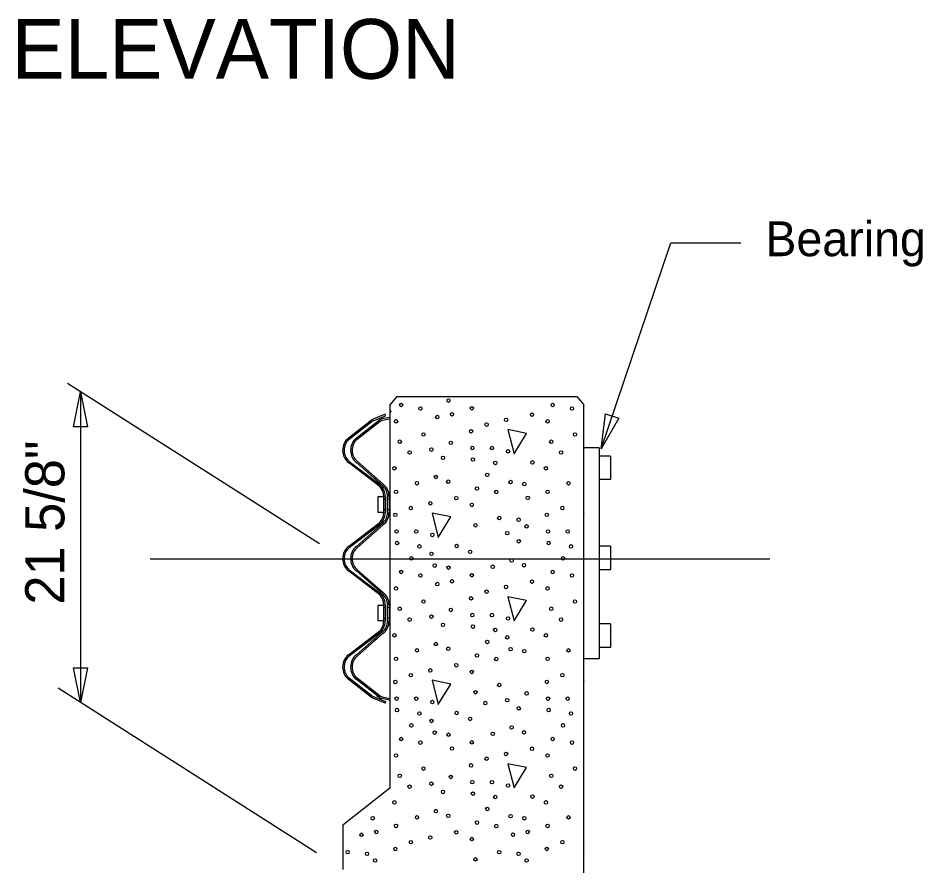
# Model space of a CAD drawing. Extents: x 0 to 34, y 0 to 22.
# Drawn here: x 10.612 to 14.256, y 4.131 to 7.539 of the extents above; entities that cross this region are included whole.
import ezdxf

# ---------------------------------------------------------------- set-up
doc = ezdxf.new("R2010")
doc.units = 0
doc.layers.add('ST_Details', color=7, linetype='Continuous')
doc.layers.add('ST_Text', color=7, linetype='Continuous')

msp = doc.modelspace()

# ---------------------------------------------------------------- linework, layer by layer
at = {"layer": 'ST_Details'}
for p, q in [((12.1322, 6.0157), (12.105, 5.9845)), ((12.8585, 6.0157), (12.1322, 6.0157)), ((12.8585, 6.0157), (12.8855, 5.9845)), ((12.105, 5.9845), (12.105, 4.4425)), ((12.8855, 2.1494), (12.8855, 5.9845)), ((12.087, 5.946), (12.0407, 5.9274)), ((12.0888, 5.9394), (12.087, 5.946)), ((11.9385, 5.85), (12.0312, 5.9229)), ((12.035, 5.9174), (11.9423, 5.8447)), ((11.9707, 5.85), (12.0633, 5.9229)), ((12.0663, 5.9174), (11.9743, 5.8447)), ((12.02, 5.9064), (12.017, 5.9112)), ((12.0423, 5.9215), (12.0888, 5.9394)), ((12.0522, 5.9064), (12.049, 5.9112)), ((12.105, 5.9334), (12.0732, 5.9277)), ((12.105, 5.927), (12.0745, 5.9215)), ((11.982, 5.8762), (11.979, 5.8809)), ((12.0142, 5.8762), (12.0103, 5.8809)), ((12.5802, 5.8844), (12.6048, 5.787)), ((12.655, 5.8692), (12.5802, 5.8844)), ((12.6048, 5.787), (12.655, 5.8692)), ((12.947, 5.8114), (12.8855, 5.8114)), ((12.947, 5.8114), (12.947, 4.9628)), ((12.9922, 5.7784), (12.947, 5.7784)), ((12.9922, 5.7784), (12.9922, 5.6834)), ((12.0603, 5.6594), (11.9392, 5.752)), ((11.9428, 5.7569), (12.0637, 5.6649)), ((12.0762, 5.6595), (11.9712, 5.752)), ((11.9747, 5.7572), (12.0793, 5.6647)), ((11.982, 5.7274), (11.9783, 5.7219)), ((12.0118, 5.7244), (12.0087, 5.7189)), ((12.0207, 5.6979), (12.017, 5.6924)), ((12.0487, 5.6917), (12.0457, 5.6864)), ((12.9922, 5.6834), (12.947, 5.6834)), ((12.081, 5.551), (12.081, 5.6155)), ((12.0872, 5.6155), (12.0872, 5.551)), ((12.0968, 5.551), (12.0968, 5.6155)), ((12.1025, 5.6155), (12.1025, 5.551)), ((12.0872, 5.6045), (12.081, 5.6045)), ((12.1025, 5.6045), (12.0968, 5.6045)), ((12.0872, 5.562), (12.081, 5.562)), ((12.1025, 5.562), (12.0968, 5.562)), ((12.2755, 5.5485), (12.3002, 5.4512)), ((12.3503, 5.5334), (12.2755, 5.5485)), ((11.9392, 5.4145), (12.0603, 5.507)), ((11.9712, 5.4145), (12.0762, 5.5072)), ((12.3002, 5.4512), (12.3503, 5.5334)), ((12.0637, 5.5017), (11.9428, 5.4097)), ((12.0793, 5.502), (11.9747, 5.4095)), ((12.0207, 5.4687), (12.017, 5.4742)), ((12.0485, 5.4749), (12.0455, 5.4802)), ((11.982, 5.4392), (11.9783, 5.4447)), ((12.0117, 5.4422), (12.0087, 5.4477)), ((12.9922, 5.4153), (12.947, 5.4153)), ((12.9922, 5.4153), (12.9922, 5.3203)), ((11.1425, 5.3654), (13.6335, 5.3654)), ((11.9428, 5.3212), (12.0637, 5.2287)), ((11.9743, 5.3212), (12.0793, 5.229)), ((12.0603, 5.2239), (11.9392, 5.3164)), ((12.0773, 5.2229), (11.9712, 5.3164)), ((11.982, 5.2917), (11.9783, 5.2862)), ((12.0117, 5.2885), (12.0087, 5.2834)), ((12.9922, 5.3203), (12.947, 5.3203)), ((12.0207, 5.2622), (12.017, 5.2567)), ((12.0485, 5.256), (12.0457, 5.2509)), ((12.5802, 5.2127), (12.6048, 5.1154)), ((12.655, 5.1975), (12.5802, 5.2127)), ((12.081, 5.1154), (12.081, 5.1799)), ((12.0872, 5.1799), (12.0872, 5.1154)), ((12.0968, 5.1154), (12.0968, 5.1799)), ((12.1025, 5.1799), (12.1025, 5.1154)), ((12.6048, 5.1154), (12.655, 5.1975)), ((12.0872, 5.169), (12.081, 5.169)), ((12.1025, 5.169), (12.0968, 5.169)), ((12.0872, 5.1264), (12.081, 5.1264)), ((12.1025, 5.1264), (12.0968, 5.1264)), ((12.9922, 5.1041), (12.947, 5.1041)), ((12.9922, 5.1041), (12.9922, 5.0091)), ((11.9392, 4.979), (12.0603, 5.0715)), ((12.0637, 5.0662), (11.9428, 4.9735)), ((11.9712, 4.979), (12.0762, 5.0714)), ((12.0793, 5.0662), (11.9743, 4.9735)), ((12.0207, 5.0332), (12.017, 5.0387)), ((12.0487, 5.0392), (12.0457, 5.0445)), ((11.982, 5.0037), (11.9783, 5.0092)), ((12.0118, 5.0065), (12.0087, 5.012)), ((12.9922, 5.0091), (12.947, 5.0091)), ((12.947, 4.9628), (12.8855, 4.9628)), ((11.9423, 4.8864), (12.035, 4.8137)), ((11.9743, 4.8864), (12.0663, 4.8137)), ((12.0312, 4.8082), (11.9385, 4.8809)), ((12.0633, 4.8082), (11.9707, 4.8809)), ((11.982, 4.8549), (11.979, 4.8494)), ((12.0142, 4.8549), (12.0103, 4.8494)), ((12.2755, 4.8769), (12.3002, 4.7795)), ((12.3503, 4.8617), (12.2755, 4.8769)), ((12.3002, 4.7795), (12.3503, 4.8617)), ((12.0203, 4.825), (12.0168, 4.8195)), ((12.0522, 4.8247), (12.049, 4.8199)), ((12.087, 4.7849), (12.0407, 4.8035)), ((12.0423, 4.8095), (12.0888, 4.7915)), ((12.105, 4.7972), (12.0732, 4.8034)), ((12.0745, 4.8095), (12.105, 4.8039)), ((12.0888, 4.7915), (12.087, 4.7849)), ((12.5802, 4.541), (12.6048, 4.4437)), ((12.655, 4.5259), (12.5802, 4.541)), ((12.6048, 4.4437), (12.655, 4.5259)), ((12.105, 4.4425), (11.9167, 4.294)), ((11.9167, 4.294), (11.9167, 4.116))]:
    msp.add_line(p, q, dxfattribs=at)
for points in [[(12.105, 5.9524), (12.1122, 5.9602)], [(12.081, 5.6142), (12.0573, 5.6142), (12.0573, 5.553), (12.081, 5.553)], [(12.8847, 5.5485), (12.8855, 5.5447)], [(12.8855, 5.5482), (12.8847, 5.5485)], [(12.081, 5.1779), (12.0573, 5.1779), (12.0573, 5.1169), (12.081, 5.1169)], [(12.8847, 4.8769), (12.8855, 4.873)], [(12.8855, 4.8765), (12.8847, 4.8769)], [(12.8847, 4.2052), (12.8855, 4.2014)], [(12.8855, 4.205), (12.8847, 4.2052)]]:
    msp.add_lwpolyline(points, dxfattribs=at)
for centre in [(12.1512, 5.9837), (12.3414, 6.0012), (12.4352, 5.9703), (12.7602, 5.9837), (12.2288, 5.9695), (12.2962, 5.935), (12.3554, 5.9459), (12.6772, 5.9447), (12.8378, 5.9695), (12.1307, 5.9175), (12.4946, 5.9048), (12.5728, 5.9238), (12.7397, 5.9175), (12.2409, 5.865), (12.4322, 5.8776), (12.8499, 5.865), (12.1455, 5.8359), (12.3508, 5.8314), (12.7545, 5.8359), (12.185, 5.7924), (12.2729, 5.8042), (12.4371, 5.8105), (12.5161, 5.8105), (12.581, 5.7969), (12.794, 5.7924), (12.3193, 5.7712), (12.4395, 5.7643), (12.6788, 5.7525), (12.1241, 5.7289), (12.5292, 5.7507), (12.7331, 5.7289), (12.2905, 5.6941), (12.4971, 5.7026), (12.2148, 5.6688), (12.3406, 5.6751), (12.4557, 5.6479), (12.5909, 5.6736), (12.646, 5.6654), (12.8238, 5.6688), (12.1307, 5.6345), (12.3727, 5.6089), (12.5333, 5.6337), (12.6599, 5.6101), (12.7397, 5.6345), (12.1901, 5.569), (12.2683, 5.588), (12.4352, 5.5817), (12.7991, 5.569), (12.1277, 5.5418), (12.7367, 5.5418), (12.45, 5.5001), (12.5454, 5.5291), (12.623, 5.5221), (12.1326, 5.4747), (12.2116, 5.4747), (12.2765, 5.4611), (12.5774, 5.4683), (12.6553, 5.4955), (12.7416, 5.4747), (12.8206, 5.4747), (12.135, 5.4284), (12.6238, 5.4354), (12.7441, 5.4284), (12.2247, 5.4148), (12.3743, 5.4166), (12.4286, 5.3931), (12.8337, 5.4148), (12.1926, 5.3668), (12.2732, 5.3849), (12.595, 5.3583), (12.8016, 5.3668), (12.2864, 5.3378), (12.3414, 5.3295), (12.5193, 5.333), (12.6451, 5.3393), (12.1512, 5.3121), (12.2288, 5.2979), (12.4352, 5.2987), (12.7602, 5.3121), (12.8378, 5.2979), (12.1307, 5.2459), (12.2962, 5.2634), (12.3554, 5.2743), (12.5728, 5.2522), (12.6772, 5.2731), (12.7397, 5.2459), (12.4322, 5.206), (12.4946, 5.2332), (12.2409, 5.1933), (12.8499, 5.1933), (12.1455, 5.1643), (12.2729, 5.1325), (12.3508, 5.1597), (12.4371, 5.1388), (12.5161, 5.1388), (12.7545, 5.1643), (12.185, 5.1207), (12.3193, 5.0996), (12.581, 5.1252), (12.794, 5.1207), (12.4395, 5.0926), (12.5292, 5.079), (12.6788, 5.0808), (12.1241, 5.0572), (12.2905, 5.0225), (12.4971, 5.0309), (12.5777, 5.0491), (12.7331, 5.0572), (12.2148, 4.9971), (12.3406, 5.0035), (12.5909, 5.0019), (12.646, 4.9937), (12.8238, 4.9971), (12.1307, 4.9629), (12.4557, 4.9763), (12.5333, 4.962), (12.7397, 4.9629), (12.2683, 4.9164), (12.3727, 4.9372), (12.1901, 4.8973), (12.4352, 4.91), (12.7991, 4.8973), (12.1277, 4.8701), (12.5454, 4.8575), (12.7367, 4.8701), (12.45, 4.8284), (12.6553, 4.8239), (12.1326, 4.803), (12.2116, 4.803), (12.2765, 4.7894), (12.4895, 4.7849), (12.5774, 4.7967), (12.7416, 4.803), (12.8206, 4.803), (12.135, 4.7568), (12.2247, 4.7432), (12.3743, 4.745), (12.6238, 4.7637), (12.7441, 4.7568), (12.8337, 4.7432), (12.1926, 4.6951), (12.2732, 4.7132), (12.4286, 4.7214), (12.8016, 4.6951), (12.2864, 4.6661), (12.3414, 4.6579), (12.5193, 4.6613), (12.595, 4.6867), (12.6451, 4.6676), (12.1512, 4.6404), (12.2288, 4.6262), (12.4352, 4.627), (12.7602, 4.6404), (12.8378, 4.6262), (12.3554, 4.6026), (12.6772, 4.6014), (12.1307, 4.5742), (12.4946, 4.5615), (12.5728, 4.5805), (12.7397, 4.5742), (12.2409, 4.5217), (12.4322, 4.5343), (12.8499, 4.5217), (12.1455, 4.4926), (12.3508, 4.4881), (12.7545, 4.4926), (12.185, 4.4491), (12.2729, 4.4609), (12.4371, 4.4672), (12.5161, 4.4672), (12.581, 4.4536), (12.794, 4.4491), (12.3193, 4.4279), (12.4395, 4.421), (12.5292, 4.4074), (12.6788, 4.4092), (12.1241, 4.3856), (12.7331, 4.3856), (12.2905, 4.3508), (12.3406, 4.3318), (12.4971, 4.3593), (12.5909, 4.3303), (12.0369, 4.3221), (12.2148, 4.3255), (12.4557, 4.3046), (12.646, 4.3221), (12.8238, 4.3255), (12.0509, 4.2668), (12.1307, 4.2912), (12.3727, 4.2656), (12.5333, 4.2904), (12.6599, 4.2668), (12.7397, 4.2912), (11.9917, 4.2559), (12.1901, 4.2257), (12.2683, 4.2447), (12.4352, 4.2384), (12.6007, 4.2559), (12.7991, 4.2257), (11.9363, 4.1858), (12.1277, 4.1985), (12.5454, 4.1858), (12.7367, 4.1985), (12.0139, 4.1788), (12.0463, 4.1522), (12.45, 4.1568), (12.623, 4.1788), (12.6553, 4.1522)]:
    msp.add_ellipse(centre, major_axis=(0, 0.00718), ratio=0.906762, dxfattribs=at)
for centre, major_axis, start_param, end_param in [((12.059, 5.867), (0, 0.0637), 0.320927, 0.501568), ((12.0574, 5.8782), (0, 0.0463), 0.364426, 0.563572), ((12.0779, 5.9001), (0, 0.0278), 0.174561, 0.619438), ((12.0779, 5.9001), (0, 0.0214), 0.174561, 0.619438), ((11.9703, 5.8012), (0, 0.0599), 0.619407, 2.535258), ((11.9703, 5.8012), (0, 0.0536), 0.619456, 2.535258), ((12.0023, 5.8012), (0, -0.0599), 3.760999, 5.67685), ((12.0023, 5.8012), (0, -0.0536), 3.761049, 5.67685), ((12.0326, 5.6155), (0, 0.0536), 4.712389, 5.676899), ((12.0326, 5.6155), (0, 0.0599), 4.712389, 5.676899), ((12.0484, 5.6155), (0, 0.0536), 4.712389, 5.676899), ((12.0484, 5.6155), (0, 0.0599), 4.712389, 5.676899), ((12.0326, 5.5512), (0, 0.0536), 3.747879, 4.712389), ((12.0326, 5.5512), (0, 0.0599), 3.747879, 4.712389), ((12.0484, 5.5512), (0, -0.0536), 0.606287, 1.570796), ((12.0484, 5.5512), (0, -0.0599), 0.606287, 1.570796), ((11.9703, 5.3655), (0, 0.0599), 0.606335, 2.535258), ((11.9703, 5.3655), (0, 0.0536), 0.606287, 2.535306), ((12.0023, 5.3655), (0, 0.0599), 0.606335, 2.535258), ((12.0023, 5.3655), (0, 0.0536), 0.606287, 2.535306), ((12.0326, 5.1798), (0, 0.0536), 4.712389, 5.676899), ((12.0326, 5.1798), (0, 0.0599), 4.712389, 5.676899), ((12.0484, 5.1798), (0, 0.0536), 4.712389, 5.676899), ((12.0484, 5.1798), (0, 0.0599), 4.712389, 5.676899), ((12.0326, 5.1155), (0, 0.0536), 3.747879, 4.712389), ((12.0326, 5.1155), (0, 0.0599), 3.747879, 4.712389), ((12.0484, 5.1155), (0, -0.0536), 0.606287, 1.570796), ((12.0484, 5.1155), (0, -0.0599), 0.606287, 1.570796), ((11.9703, 4.9298), (0, 0.0599), 0.606335, 2.522186), ((11.9703, 4.9298), (0, 0.0536), 0.606335, 2.522137), ((12.0023, 4.9298), (0, 0.0599), 0.606335, 2.522186), ((12.0023, 4.9298), (0, 0.0536), 0.606335, 2.522137), ((12.0574, 4.8528), (0, -0.0463), 5.719613, 5.91876), ((12.0753, 4.8528), (0, -0.0463), 5.719613, 5.91876), ((12.0779, 4.8309), (0, -0.0214), 5.663747, 6.108625), ((12.059, 4.864), (0, -0.0637), 5.781617, 5.962258), ((12.0779, 4.8309), (0, -0.0278), 5.663747, 6.108625)]:
    msp.add_ellipse(centre, major_axis=major_axis, ratio=0.906762, start_param=start_param, end_param=end_param, dxfattribs=at)
at = {"layer": 'ST_Text'}
for p, q in [((11.8233, 5.4249), (10.81, 6.0698)), ((10.8627, 6.0363), (10.8627, 4.7873)), ((11.8112, 4.1832), (10.7722, 4.8449))]:
    msp.add_line(p, q, dxfattribs=at)
msp.add_lwpolyline([(12.9546, 5.8069), (13.2352, 6.6352), (13.5159, 6.6352)], dxfattribs=at)
for points in [[(10.8907, 5.8963), (10.8347, 5.8963), (10.8627, 6.0363)], [(12.973, 5.9484), (13.026, 5.9305), (12.9546, 5.8069)], [(10.8347, 4.9273), (10.8907, 4.9273), (10.8627, 4.7873)]]:
    msp.add_lwpolyline(points, close=True, dxfattribs=at)

# ---------------------------------------------------------------- texts
for s, height, p in [('ELEVATION', 0.24, (10.5853, 7.2952)), ('Bearing Plate', 0.14, (13.615, 6.5817))]:
    msp.add_text(s, height=height, dxfattribs=at).set_placement(p)
msp.add_text('21 5/8"', height=0.1574, rotation=90, dxfattribs=at).set_placement((10.7976, 5.1808))

doc.saveas('drawing.dxf')
